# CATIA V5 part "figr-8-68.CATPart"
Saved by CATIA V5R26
Part number: Part1
Bounding box of the stored display mesh (mm): x -84.762 to 84.762, y -75 to 75, z 0 to 50
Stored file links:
  D:\_Deepak\CATIA\CATIA V5-6R2016_Deepak\Resources\Part files\Partfiles\c08_catia_v5_6r2016_prt\figr-8-68.CATPart
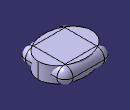
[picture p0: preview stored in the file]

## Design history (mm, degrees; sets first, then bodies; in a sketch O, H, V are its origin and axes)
Body1 (main body)
  Sketch1 on xy-plane, origin (0, 0, 0), H (1, 0, 0), V (0, 1, 0)
    line L1 (-75, 75) -> (75, 75)
    line L2 (75, 75) -> (75, -75)
    line L3 (75, -75) -> (-75, -75)
    line L4 (-75, -75) -> (-75, 75)
    axis line L5 (75, -75) -> (-75, 75)
    length L3 = 150
    length L2 = 150
    horizontal: L1 H, L3 H
    vertical: L2 V, L4 V
    midpoint: O L5
  Pad1: profile Sketch1, direction (0, 0, 1), length 50
  Fillet1: radius 25, on face of Pad1 (x6)
Body2
  Sketch2 on xy-plane, origin (0, 0, 0), H (1, 0, 0), V (0, 1, 0)
    ellipse A1 centre (0, 0) semi-axes 84.7617, 65.8627 rotation 0
    point P1 (84.7617, 0)
    point P2 (0, 65.8627)
    coincidence: P1 H, P2 V, A1 P1, A1 P2
  Pad2: profile Sketch2, direction (0, 0, 1), length 50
